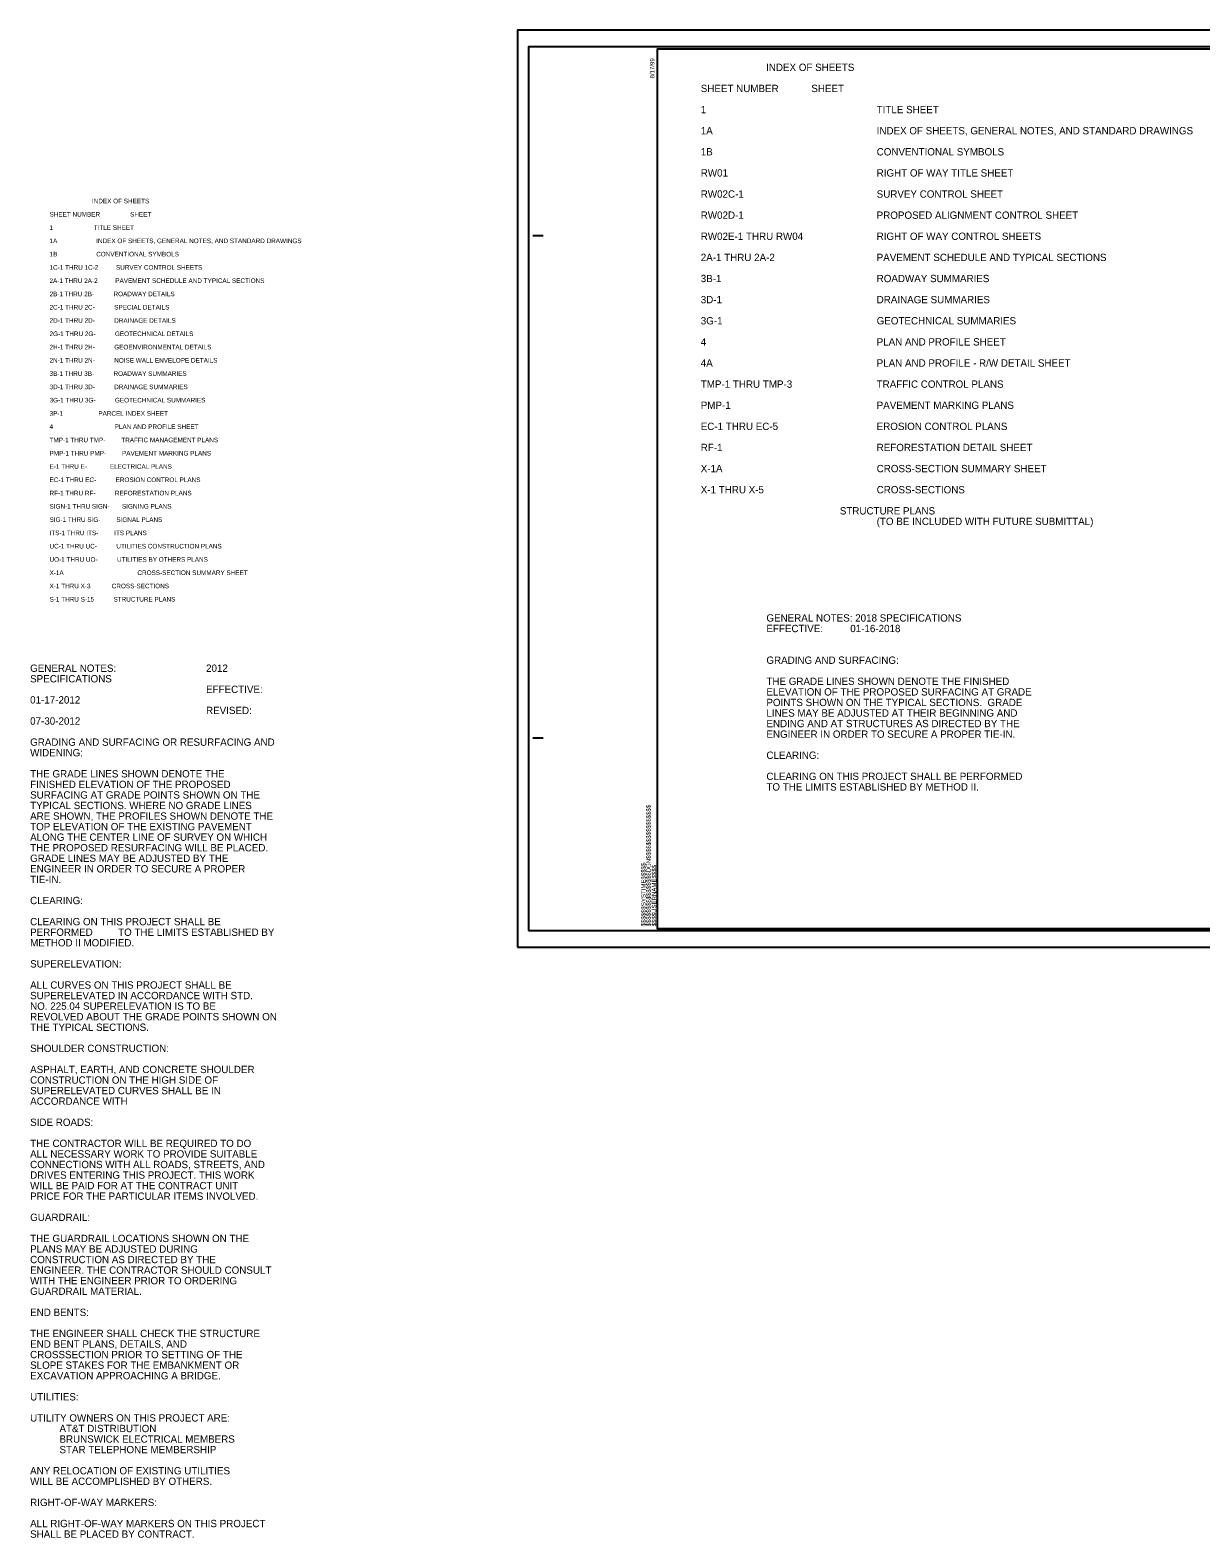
# Model space of a CAD drawing. Extents: x 2486563 to 2488026, y 371425 to 372193.
# Drawn here: x 2486563 to 2487122, y 371425 to 372145 of the extents above; entities that cross this region are included whole.
import ezdxf

# ---------------------------------------------------------------- set-up
doc = ezdxf.new("R2010")
doc.units = 0
for name, color, linetype in [('Sheet Cutting Line CELL', 7, 'Continuous'), ('Sheet Data Text CELL', 7, 'Continuous'), ('Sheet Plan CELL', 7, 'Continuous'), ('Sheet Plot Border Inside CELL', 7, 'Continuous'), ('Sheet Plot Border Outside CELL', 7, 'Continuous'), ('Text', 7, 'Continuous')]:
    doc.layers.add(name, color=color, linetype=linetype)

msp = doc.modelspace()

# ---------------------------------------------------------------- linework, layer by layer
at = {"layer": 'Sheet Cutting Line CELL'}
for p, q in [((2487469.29, 372145.11), (2486795.89, 372145.11)), ((2486795.89, 372145.11), (2486795.89, 371707.11)), ((2486795.89, 371707.11), (2487469.29, 371707.11))]:
    msp.add_line(p, q, dxfattribs=at)
at = {"layer": 'Sheet Plan CELL'}
for p, q in [((2486862.49, 372136.11), (2486862.49, 372136.11)), ((2486803.09, 372047.11), (2486808.09, 372047.11)), ((2486803.09, 371807.11), (2486808.09, 371807.11)), ((2486862.49, 371716.11), (2486862.49, 371716.11))]:
    msp.add_line(p, q, dxfattribs=at)
msp.add_lwpolyline([(2487462.49, 372136.11), (2486862.49, 372136.11), (2486862.49, 371716.11), (2487462.49, 371716.11)], close=True, dxfattribs=at)
at = {"layer": 'Sheet Plot Border Inside CELL'}
msp.add_lwpolyline([(2486801.09, 371715.11), (2487467.49, 371715.11), (2487467.49, 372137.11), (2486801.09, 372137.11)], close=True, dxfattribs=at)
at = {"layer": 'Sheet Plot Border Outside CELL'}
msp.add_lwpolyline([(2486795.89, 371707.11), (2487469.29, 371707.11), (2487469.29, 372145.11), (2486795.89, 372145.11)], close=True, dxfattribs=at)

# ---------------------------------------------------------------- texts
at = {"layer": 'Sheet Data Text CELL'}
for s, p in [('                        INDEX OF SHEETS ', (2486572.38, 372062.4)), ('SHEET NUMBER                 SHEET   ', (2486572.38, 372056.06)), ('1                       TITLE SHEET', (2486572.38, 372049.72)), ('1A                      INDEX OF SHEETS, GENERAL NOTES, AND STANDARD DRAWINGS', (2486572.38, 372043.38)), ('1B                      CONVENTIONAL SYMBOLS ', (2486572.38, 372037.04)), ('1C-1 THRU 1C-2          SURVEY CONTROL SHEETS', (2486572.38, 372030.7)), ('2A-1 THRU 2A-2          PAVEMENT SCHEDULE AND TYPICAL SECTIONS', (2486572.38, 372024.36)), ('2B-1 THRU 2B-           ROADWAY DETAILS', (2486572.38, 372018.02)), ('2C-1 THRU 2C-           SPECIAL DETAILS', (2486572.38, 372011.68)), ('2D-1 THRU 2D-           DRAINAGE DETAILS', (2486572.38, 372005.34)), ('2G-1 THRU 2G-           GEOTECHNICAL DETAILS', (2486572.38, 371999)), ('2H-1 THRU 2H-           GEOENVIRONMENTAL DETAILS', (2486572.38, 371992.66)), ('2N-1 THRU 2N-           NOISE WALL ENVELOPE DETAILS', (2486572.38, 371986.32)), ('3B-1 THRU 3B-           ROADWAY SUMMARIES', (2486572.38, 371979.98)), ('3D-1 THRU 3D-           DRAINAGE SUMMARIES', (2486572.38, 371973.64)), ('3G-1 THRU 3G-           GEOTECHNICAL SUMMARIES', (2486572.38, 371967.3)), ('3P-1                    PARCEL INDEX SHEET', (2486572.38, 371960.96)), ('4 ', (2486572.38, 371954.62)), ('                PLAN AND PROFILE SHEET', (2486589.98, 371954.62)), ('TMP-1 THRU TMP-         TRAFFIC MANAGEMENT PLANS', (2486572.38, 371948.28)), ('PMP-1 THRU PMP-         PAVEMENT MARKING PLANS', (2486572.38, 371941.94)), ('E-1 THRU E-             ELECTRICAL PLANS', (2486572.38, 371935.6)), ('EC-1 THRU EC-           EROSION CONTROL PLANS', (2486572.38, 371929.26)), ('RF-1 THRU RF-           REFORESTATION PLANS', (2486572.38, 371922.92)), ('SIGN-1 THRU SIGN-       SIGNING PLANS', (2486572.38, 371916.58)), ('SIG-1 THRU SIG-         SIGNAL PLANS', (2486572.38, 371910.24)), ('ITS-1 THRU ITS-         ITS PLANS', (2486572.38, 371903.9)), ('UC-1 THRU UC-           UTILITIES CONSTRUCTION PLANS', (2486572.38, 371897.56)), ('X-1A ', (2486572.38, 371884.88)), ('UO-1 THRU UO-           UTILITIES BY OTHERS PLANS', (2486572.38, 371891.22)), ('        CROSS-SECTION SUMMARY SHEET', (2486607.58, 371884.88)), ('X-1 THRU X-3            CROSS-SECTIONS', (2486572.38, 371878.54)), ('S-1 THRU S-15           STRUCTURE PLANS', (2486572.38, 371872.2))]:
    msp.add_text(s, height=2.2, dxfattribs=at).set_placement(p)
at = {"layer": 'Sheet Plan CELL'}
for s, p in [('8/17/99', (2486861.19, 372122.03)), ('$$$$$$$$$$$$$$$$DGN$$$$$$$$$$$$$$$$', (2486859.43, 371717.06)), ('$$$$$$SYSTIME$$$$$', (2486857.01, 371717.06)), ('$$$$USERNAME$$$$', (2486862.06, 371717.06))]:
    msp.add_text(s, height=2.1, rotation=90, dxfattribs=at).set_placement(p)
at = {"layer": 'Text'}
for s, p in [('                        INDEX OF SHEETS ', (2486883.33, 372125.61)), ('SHEET NUMBER            SHEET   ', (2486883.33, 372115.53)), ('1', (2486883.33, 372105.44)), ('TITLE SHEET', (2486967.33, 372105.44)), ('1A', (2486883.33, 372095.35)), ('INDEX OF SHEETS, GENERAL NOTES, AND STANDARD DRAWINGS', (2486967.33, 372095.35)), ('1B', (2486883.33, 372085.27)), ('CONVENTIONAL SYMBOLS', (2486967.33, 372085.27)), ('RW01', (2486883.33, 372075.18)), ('RIGHT OF WAY TITLE SHEET ', (2486967.33, 372075.18)), ('RW02C-1', (2486883.33, 372065.09)), ('SURVEY CONTROL SHEET', (2486967.33, 372065.09)), ('RW02D-1', (2486883.33, 372055.01)), ('PROPOSED ALIGNMENT CONTROL SHEET', (2486967.33, 372055.01)), ('RW02E-1 THRU RW04', (2486883.33, 372044.92)), ('RIGHT OF WAY CONTROL SHEETS', (2486967.33, 372044.92)), ('2A-1 THRU 2A-2', (2486883.33, 372034.83)), ('PAVEMENT SCHEDULE AND TYPICAL SECTIONS', (2486967.33, 372034.83)), ('3B-1  ', (2486883.33, 372024.75)), ('ROADWAY SUMMARIES', (2486967.33, 372024.75)), ('3D-1', (2486883.33, 372014.66)), ('DRAINAGE SUMMARIES', (2486967.33, 372014.66)), ('3G-1', (2486883.33, 372004.57)), ('GEOTECHNICAL SUMMARIES', (2486967.33, 372004.57)), ('4', (2486883.33, 371994.49)), ('PLAN AND PROFILE SHEET', (2486967.33, 371994.49)), ('4A', (2486883.33, 371984.4)), ('PLAN AND PROFILE - R/W DETAIL SHEET', (2486967.33, 371984.4)), ('TMP-1 THRU TMP-3', (2486883.33, 371974.31)), ('TRAFFIC CONTROL PLANS', (2486967.33, 371974.31)), ('PMP-1', (2486883.33, 371964.23)), ('PAVEMENT MARKING PLANS', (2486967.33, 371964.23)), ('EC-1 THRU EC-5', (2486883.33, 371954.14)), ('EROSION CONTROL PLANS', (2486967.33, 371954.14)), ('RF-1', (2486883.33, 371944.05)), ('REFORESTATION DETAIL SHEET', (2486967.33, 371944.05)), ('X-1A         ', (2486883.33, 371933.97)), ('CROSS-SECTION SUMMARY SHEET', (2486967.33, 371933.97)), ('X-1 THRU X-5', (2486883.33, 371923.88)), ('CROSS-SECTIONS', (2486967.33, 371923.88)), ('        STRUCTURE PLANS', (2486939.33, 371913.79)), ('(TO BE INCLUDED WITH FUTURE SUBMITTAL)', (2486967.33, 371908.75)), ('GENERAL NOTES: 2018 SPECIFICATIONS', (2486914.68, 371862.63)), ('EFFECTIVE:          01-16-2018', (2486914.68, 371857.59)), ('GRADING AND SURFACING: ', (2486914.68, 371842.46)), ('SPECIFICATIONS', (2486563.12, 371833.59)), ('GENERAL NOTES: ', (2486563.12, 371838.63)), ('2012 ', (2486647.12, 371838.63)), ('EFFECTIVE: ', (2486647.12, 371828.54)), ('THE GRADE LINES SHOWN DENOTE THE FINISHED', (2486914.68, 371832.37)), ('ELEVATION OF THE PROPOSED SURFACING AT GRADE ', (2486914.68, 371827.33)), ('01-17-2012', (2486563.12, 371823.5)), ('POINTS SHOWN ON THE TYPICAL SECTIONS.  GRADE ', (2486914.68, 371822.28)), ('07-30-2012', (2486563.12, 371813.41)), ('REVISED: ', (2486647.12, 371818.46)), ('LINES MAY BE ADJUSTED AT THEIR BEGINNING AND ', (2486914.68, 371817.24)), ('ENDING AND AT STRUCTURES AS DIRECTED BY THE ', (2486914.68, 371812.2)), ('ENGINEER IN ORDER TO SECURE A PROPER TIE-IN.  ', (2486914.68, 371807.15)), ('WIDENING:', (2486563.12, 371798.28)), ('GRADING AND SURFACING OR RESURFACING AND ', (2486563.12, 371803.33)), ('CLEARING:', (2486914.68, 371797.07)), ('THE GRADE LINES SHOWN DENOTE THE ', (2486563.12, 371788.2)), ('FINISHED ELEVATION OF THE PROPOSED ', (2486563.12, 371783.15)), ('CLEARING ON THIS PROJECT SHALL BE PERFORMED ', (2486914.68, 371786.98)), ('SURFACING AT GRADE POINTS SHOWN ON THE ', (2486563.12, 371778.11)), ('TO THE LIMITS ESTABLISHED BY METHOD II.', (2486914.68, 371781.94)), ('TYPICAL SECTIONS. WHERE NO GRADE LINES ', (2486563.12, 371773.07)), ('ARE SHOWN, THE PROFILES SHOWN DENOTE THE ', (2486563.12, 371768.02)), ('TOP ELEVATION OF THE EXISTING PAVEMENT ', (2486563.12, 371762.98)), ('ALONG THE CENTER LINE OF SURVEY ON WHICH ', (2486563.12, 371757.94)), ('THE PROPOSED RESURFACING WILL BE PLACED. ', (2486563.12, 371752.89)), ('GRADE LINES MAY BE ADJUSTED BY THE ', (2486563.12, 371747.85)), ('ENGINEER IN ORDER TO SECURE A PROPER ', (2486563.12, 371742.81)), ('TIE-IN.', (2486563.12, 371737.76)), ('CLEARING:', (2486563.12, 371727.68)), ('CLEARING ON THIS PROJECT SHALL BE ', (2486563.12, 371717.59)), ('PERFORMED ', (2486563.12, 371712.55)), ('TO THE LIMITS ESTABLISHED BY ', (2486605.12, 371712.55)), ('METHOD II MODIFIED.', (2486563.12, 371707.51)), ('SUPERELEVATION:', (2486563.12, 371697.42)), ('ALL CURVES ON THIS PROJECT SHALL BE ', (2486563.12, 371687.33)), ('SUPERELEVATED IN ACCORDANCE WITH STD.', (2486563.12, 371682.29)), ('NO. 225.04 SUPERELEVATION IS TO BE ', (2486563.12, 371677.25)), ('REVOLVED ABOUT THE GRADE POINTS SHOWN ON ', (2486563.12, 371672.2)), ('THE TYPICAL SECTIONS.', (2486563.12, 371667.16)), ('SHOULDER CONSTRUCTION:', (2486563.12, 371657.07)), ('ASPHALT, EARTH, AND CONCRETE SHOULDER ', (2486563.12, 371646.99)), ('CONSTRUCTION ON THE HIGH SIDE OF ', (2486563.12, 371641.94)), ('ACCORDANCE WITH', (2486563.12, 371631.86)), ('SUPERELEVATED CURVES SHALL BE IN ', (2486563.12, 371636.9)), ('SIDE ROADS:', (2486563.12, 371621.77)), ('THE CONTRACTOR WILL BE REQUIRED TO DO ', (2486563.12, 371611.68)), ('ALL NECESSARY WORK TO PROVIDE SUITABLE ', (2486563.12, 371606.64)), ('CONNECTIONS WITH ALL ROADS, STREETS, AND ', (2486563.12, 371601.6)), ('DRIVES ENTERING THIS PROJECT. THIS WORK ', (2486563.12, 371596.55)), ('WILL BE PAID FOR AT THE CONTRACT UNIT ', (2486563.12, 371591.51)), ('PRICE FOR THE PARTICULAR ITEMS INVOLVED.', (2486563.12, 371586.47)), ('GUARDRAIL:', (2486563.12, 371576.38)), ('THE GUARDRAIL LOCATIONS SHOWN ON THE ', (2486563.12, 371566.29)), ('PLANS MAY BE ADJUSTED DURING ', (2486563.12, 371561.25)), ('CONSTRUCTION AS DIRECTED BY THE ', (2486563.12, 371556.21)), ('WITH THE ENGINEER PRIOR TO ORDERING ', (2486563.12, 371546.12)), ('ENGINEER. THE CONTRACTOR SHOULD CONSULT ', (2486563.12, 371551.16)), ('GUARDRAIL MATERIAL.', (2486563.12, 371541.08)), ('END BENTS:', (2486563.12, 371530.99)), ('THE ENGINEER SHALL CHECK THE STRUCTURE ', (2486563.12, 371520.9)), ('CROSSSECTION PRIOR TO SETTING OF THE ', (2486563.12, 371510.82)), ('END BENT PLANS, DETAILS, AND ', (2486563.12, 371515.86)), ('SLOPE STAKES FOR THE EMBANKMENT OR ', (2486563.12, 371505.77)), ('EXCAVATION APPROACHING A BRIDGE.', (2486563.12, 371500.73)), ('UTILITIES:', (2486563.12, 371490.64)), ('UTILITY OWNERS ON THIS PROJECT ARE:', (2486563.12, 371480.56)), ('AT&T DISTRIBUTION', (2486577.12, 371475.51)), ('BRUNSWICK ELECTRICAL MEMBERS', (2486577.12, 371470.47)), ('STAR TELEPHONE MEMBERSHIP', (2486577.12, 371465.43)), ('ANY RELOCATION OF EXISTING UTILITIES ', (2486563.12, 371455.34)), ('WILL BE ACCOMPLISHED BY OTHERS.', (2486563.12, 371450.3)), ('RIGHT-OF-WAY MARKERS:', (2486563.12, 371440.21)), ('ALL RIGHT-OF-WAY MARKERS ON THIS PROJECT ', (2486563.12, 371430.12)), ('SHALL BE PLACED BY CONTRACT.', (2486563.12, 371425.08))]:
    msp.add_text(s, height=3.5, dxfattribs=at).set_placement(p)

doc.saveas('drawing.dxf')
